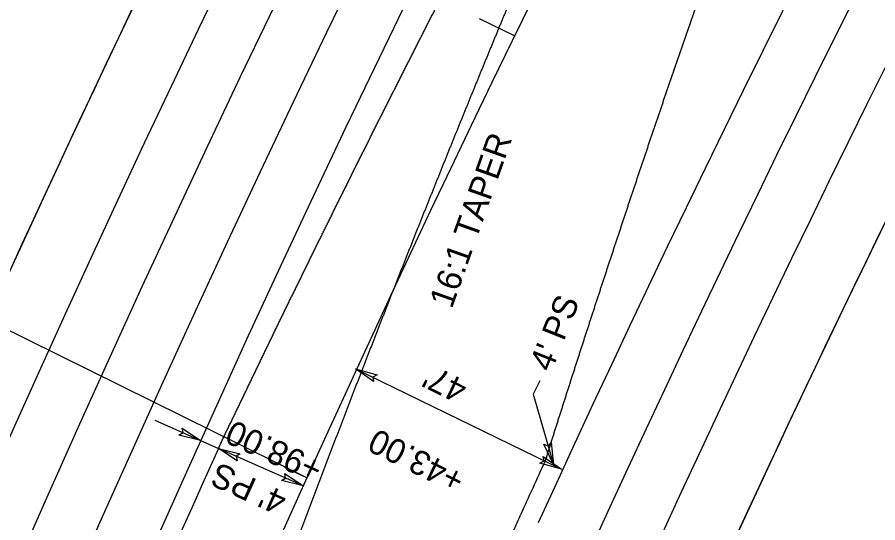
# Model space of a CAD drawing. Extents: x 2389099 to 2405615, y 552200 to 573532.
# Drawn here: x 2395482.3 to 2395658.7, y 556915.3 to 557018.8 of the extents above; entities that cross this region are included whole.
import ezdxf

# ---------------------------------------------------------------- set-up
doc = ezdxf.new("R2010")
doc.units = 0
for name, color, linetype in [('Prop Cable Guiderail Single Face', 7, 'Continuous'), ('Prop Dimension', 7, 'Continuous'), ('Prop Dimension Text', 7, 'Continuous'), ('Prop DSN Text', 7, 'Continuous'), ('Prop EOT', 7, 'Continuous'), ('Prop Guardrail', 7, 'Continuous'), ('Prop Horizontal Alignment', 7, 'Continuous'), ('Prop Horizontal Alignment Tick Large', 7, 'Continuous'), ('Prop Horizontal Alignment Tick Small', 7, 'Continuous'), ('Prop Lane Lines', 7, 'Continuous'), ('Prop SBG', 7, 'Continuous')]:
    doc.layers.add(name, color=color, linetype=linetype)

msp = doc.modelspace()

# ---------------------------------------------------------------- linework, layer by layer
at = {"layer": 'Prop Cable Guiderail Single Face'}
for points in [[(2395600.36, 557062.59), (2395600.06, 557061.88), (2395599.75, 557061.17), (2395599.44, 557060.45), (2395599.14, 557059.74), (2395598.83, 557059.03), (2395598.53, 557058.31), (2395598.22, 557057.6), (2395597.92, 557056.88), (2395597.61, 557056.17), (2395597.31, 557055.46), (2395597, 557054.74), (2395596.7, 557054.03), (2395596.4, 557053.32), (2395596.09, 557052.61), (2395595.79, 557051.89), (2395595.48, 557051.18), (2395595.18, 557050.47), (2395594.88, 557049.76), (2395594.57, 557049.04), (2395594.27, 557048.32), (2395593.97, 557047.61), (2395593.67, 557046.9), (2395593.36, 557046.18), (2395593.06, 557045.47), (2395592.76, 557044.76), (2395592.46, 557044.05), (2395592.15, 557043.33), (2395591.85, 557042.61), (2395591.55, 557041.9), (2395591.25, 557041.19), (2395590.95, 557040.47), (2395590.65, 557039.76), (2395590.35, 557039.04), (2395590.05, 557038.33), (2395589.75, 557037.61), (2395589.45, 557036.9), (2395589.15, 557036.19), (2395588.85, 557035.47), (2395588.55, 557034.76), (2395588.25, 557034.04), (2395587.95, 557033.33), (2395587.65, 557032.61), (2395587.35, 557031.9), (2395587.05, 557031.18), (2395586.75, 557030.47), (2395586.45, 557029.75), (2395586.16, 557029.04), (2395585.85, 557028.32), (2395585.56, 557027.61), (2395585.26, 557026.89), (2395584.96, 557026.18), (2395584.66, 557025.46), (2395584.37, 557024.75), (2395584.07, 557024.03), (2395583.77, 557023.32), (2395583.47, 557022.6), (2395583.18, 557021.88), (2395582.88, 557021.17), (2395582.59, 557020.46), (2395582.29, 557019.73), (2395581.99, 557019.02), (2395581.7, 557018.31), (2395581.4, 557017.59), (2395581.1, 557016.87), (2395580.81, 557016.16), (2395580.51, 557015.44), (2395580.22, 557014.73), (2395579.92, 557014), (2395579.63, 557013.29), (2395579.33, 557012.58), (2395579.04, 557011.86), (2395578.74, 557011.14), (2395578.45, 557010.42), (2395578.15, 557009.71)], [(2395578.15, 557009.71), (2395577.86, 557008.99), (2395577.57, 557008.28), (2395577.27, 557007.56), (2395576.98, 557006.84), (2395576.69, 557006.13), (2395576.39, 557005.41), (2395576.1, 557004.69), (2395575.81, 557003.97), (2395575.51, 557003.26), (2395575.22, 557002.54), (2395574.93, 557001.82), (2395574.64, 557001.1), (2395574.35, 557000.39), (2395574.05, 556999.67), (2395573.76, 556998.95), (2395573.47, 556998.24), (2395573.18, 556997.52), (2395572.89, 556996.8), (2395572.59, 556996.08), (2395572.3, 556995.36), (2395572.01, 556994.65), (2395571.72, 556993.93), (2395571.43, 556993.21), (2395571.14, 556992.49), (2395570.85, 556991.78), (2395570.56, 556991.06), (2395570.27, 556990.34), (2395569.98, 556989.62), (2395569.69, 556988.9), (2395569.41, 556988.19), (2395569.11, 556987.46), (2395568.83, 556986.75), (2395568.54, 556986.03), (2395568.25, 556985.31), (2395567.96, 556984.59), (2395567.67, 556983.87), (2395567.38, 556983.16), (2395567.1, 556982.44), (2395566.81, 556981.72), (2395566.52, 556981), (2395566.23, 556980.28), (2395565.95, 556979.56), (2395565.66, 556978.85), (2395565.37, 556978.12), (2395565.08, 556977.4), (2395564.8, 556976.69), (2395564.51, 556975.97), (2395564.22, 556975.24), (2395563.94, 556974.53), (2395563.65, 556973.81), (2395563.37, 556973.09), (2395563.08, 556972.37), (2395562.8, 556971.65), (2395562.51, 556970.93), (2395562.23, 556970.22), (2395561.94, 556969.49), (2395561.65, 556968.77), (2395561.37, 556968.05), (2395561.09, 556967.34), (2395560.8, 556966.61), (2395560.52, 556965.89), (2395560.23, 556965.17), (2395559.95, 556964.46), (2395559.66, 556963.73), (2395559.38, 556963.01), (2395559.1, 556962.29), (2395558.82, 556961.58), (2395558.53, 556960.85), (2395558.25, 556960.13), (2395557.97, 556959.41), (2395557.69, 556958.69), (2395557.4, 556957.97), (2395557.12, 556957.25), (2395556.84, 556956.53)], [(2395556.84, 556956.53), (2395556.56, 556955.81), (2395556.28, 556955.09), (2395555.99, 556954.36), (2395555.71, 556953.65), (2395555.43, 556952.93), (2395555.15, 556952.21), (2395554.87, 556951.48), (2395554.59, 556950.76), (2395554.31, 556950.04), (2395554.03, 556949.32), (2395553.74, 556948.6), (2395553.46, 556947.88), (2395553.19, 556947.16), (2395552.91, 556946.44), (2395552.62, 556945.71), (2395552.35, 556944.99), (2395552.07, 556944.27), (2395551.79, 556943.55), (2395551.51, 556942.82), (2395551.23, 556942.11), (2395550.95, 556941.39), (2395550.67, 556940.67), (2395550.39, 556939.94), (2395550.12, 556939.22), (2395549.84, 556938.5), (2395549.56, 556937.78), (2395549.28, 556937.05), (2395549, 556936.33), (2395548.73, 556935.61), (2395548.45, 556934.89), (2395548.17, 556934.16), (2395547.9, 556933.44), (2395547.62, 556932.72), (2395547.34, 556932), (2395547.06, 556931.27), (2395546.79, 556930.55), (2395546.51, 556929.83), (2395546.24, 556929.11), (2395545.97, 556928.39), (2395545.69, 556927.66), (2395545.41, 556926.94), (2395545.14, 556926.22), (2395544.86, 556925.5), (2395544.59, 556924.77), (2395544.31, 556924.05), (2395544.04, 556923.33), (2395543.76, 556922.61), (2395543.49, 556921.88), (2395543.21, 556921.16), (2395542.94, 556920.43), (2395542.67, 556919.71), (2395542.39, 556918.98), (2395542.12, 556918.26), (2395541.85, 556917.54), (2395541.58, 556916.82), (2395541.3, 556916.09), (2395541.03, 556915.37), (2395540.76, 556914.65), (2395540.48, 556913.93), (2395540.21, 556913.19), (2395539.94, 556912.47), (2395539.67, 556911.75), (2395539.4, 556911.03), (2395539.12, 556910.3), (2395538.85, 556909.58), (2395538.58, 556908.86), (2395538.31, 556908.13), (2395538.04, 556907.4), (2395537.77, 556906.68), (2395537.5, 556905.96), (2395537.23, 556905.24), (2395536.95, 556904.51), (2395536.42, 556903.06)]]:
    msp.add_spline(points, degree=3, dxfattribs=at)
at = {"layer": 'Prop Dimension'}
for p, q in [((2395551.61, 556946.84), (2395593.85, 556926.23)), ((2395589.43, 556944.33), (2395588.08, 556941.6)), ((2395588.08, 556941.6), (2395592.22, 556927.2)), ((2395510.47, 556936.31), (2395523.53, 556930.52)), ((2395540.9, 556922.82), (2395523.53, 556930.52))]:
    msp.add_line(p, q, dxfattribs=at)
for points in [[(2395555.33, 556944.19), (2395551.61, 556946.84), (2395556.04, 556945.6), (2395555.17, 556945.13)], [(2395516.07, 556934.67), (2395519.87, 556932.14), (2395515.41, 556933.24), (2395516.26, 556933.74)], [(2395591.73, 556931.74), (2395592.22, 556927.2), (2395590.21, 556931.34), (2395591.14, 556931)], [(2395527.33, 556927.99), (2395523.53, 556930.52), (2395527.99, 556929.42), (2395527.14, 556928.92)], [(2395590.13, 556928.88), (2395593.85, 556926.23), (2395589.43, 556927.47), (2395590.29, 556927.94)], [(2395537.1, 556925.35), (2395540.9, 556922.82), (2395536.44, 556923.92), (2395537.29, 556924.42)]]:
    msp.add_lwpolyline(points, close=True, dxfattribs=at)
at = {"layer": 'Prop DSN Text'}
msp.add_line((2395541.67, 556924.51), (2395466.55, 556961.59), dxfattribs=at)
at = {"layer": 'Prop EOT'}
msp.add_line((2395523.56, 556930.54), (2395523.3, 556930), dxfattribs=at)
for centre, radius, start, end in [((2398729.82, 555480.32), 3559, 136.54853, 163.17888), ((2398729.82, 555480.32), 3523, 136.54853, 169.40696), ((2398729.82, 555480.32), 3453, 136.54853, 155.44499), ((2398729.82, 555480.32), 3429, 136.54853, 155.44499), ((2398729.82, 555480.32), 3573, 151.19964, 163.17888), ((2398729.83, 555480.34), 3415, 150.73536, 155.44499), ((2398729.82, 555480.32), 3519, 155.66284, 169.40696), ((2398729.82, 555480.32), 3457, 155.2472, 155.44499)]:
    msp.add_arc(centre, radius, start, end, dxfattribs=at)
for points in [[(2395553, 556990.89), (2395553.41, 556991.7), (2395553.81, 556992.51), (2395554.22, 556993.32), (2395554.63, 556994.13), (2395555.03, 556994.94), (2395555.44, 556995.75), (2395555.85, 556996.56), (2395556.26, 556997.38), (2395556.66, 556998.19), (2395557.07, 556999), (2395557.48, 556999.81), (2395557.89, 557000.62), (2395558.3, 557001.43), (2395558.7, 557002.24), (2395559.11, 557003.05), (2395559.52, 557003.86), (2395559.93, 557004.67), (2395560.34, 557005.48), (2395560.75, 557006.29), (2395561.16, 557007.1), (2395561.57, 557007.91), (2395561.98, 557008.72), (2395562.39, 557009.53), (2395562.8, 557010.34), (2395563.21, 557011.15), (2395563.63, 557011.95), (2395564.04, 557012.76), (2395564.45, 557013.57), (2395564.86, 557014.38), (2395565.27, 557015.19), (2395565.69, 557016), (2395566.1, 557016.81), (2395566.51, 557017.61), (2395566.92, 557018.42), (2395567.34, 557019.23), (2395567.75, 557020.04), (2395568.16, 557020.85), (2395568.58, 557021.65), (2395568.99, 557022.46), (2395569.4, 557023.27), (2395569.82, 557024.08), (2395570.23, 557024.88), (2395570.65, 557025.69), (2395571.06, 557026.5), (2395571.48, 557027.3), (2395571.89, 557028.11), (2395572.31, 557028.92), (2395572.73, 557029.72), (2395573.14, 557030.53), (2395573.56, 557031.34), (2395573.97, 557032.14), (2395574.39, 557032.95), (2395574.81, 557033.75), (2395575.22, 557034.56), (2395575.64, 557035.37), (2395576.06, 557036.17), (2395576.48, 557036.98), (2395576.89, 557037.78), (2395577.31, 557038.59), (2395577.73, 557039.39), (2395578.15, 557040.2), (2395578.57, 557041), (2395578.99, 557041.81), (2395579.41, 557042.61), (2395579.82, 557043.42), (2395580.24, 557044.22), (2395580.66, 557045.03), (2395581.08, 557045.83), (2395581.5, 557046.64), (2395581.92, 557047.44), (2395582.34, 557048.24), (2395582.77, 557049.05), (2395583.19, 557049.85), (2395583.61, 557050.65)], [(2395629.58, 557044.33), (2395629.3, 557043.54), (2395629.02, 557042.76), (2395628.75, 557041.98), (2395628.47, 557041.19), (2395628.19, 557040.4), (2395627.91, 557039.62), (2395627.63, 557038.84), (2395627.36, 557038.06), (2395627.08, 557037.26), (2395626.8, 557036.48), (2395626.53, 557035.7), (2395626.25, 557034.92), (2395625.97, 557034.13), (2395625.69, 557033.34), (2395625.42, 557032.56), (2395625.14, 557031.77), (2395624.87, 557030.99), (2395624.59, 557030.2), (2395624.32, 557029.42), (2395624.04, 557028.63), (2395623.76, 557027.85), (2395623.49, 557027.06), (2395623.22, 557026.28), (2395622.94, 557025.49), (2395622.67, 557024.7), (2395622.39, 557023.92), (2395622.12, 557023.14), (2395621.84, 557022.35), (2395621.57, 557021.56), (2395621.3, 557020.78), (2395621.03, 557020), (2395620.75, 557019.2), (2395620.48, 557018.42), (2395620.21, 557017.64), (2395619.93, 557016.84), (2395619.66, 557016.06), (2395619.39, 557015.28), (2395619.12, 557014.49), (2395618.85, 557013.7), (2395618.57, 557012.92), (2395618.3, 557012.13), (2395618.04, 557011.35), (2395617.76, 557010.56), (2395617.49, 557009.77), (2395617.22, 557008.99), (2395616.95, 557008.2), (2395616.68, 557007.41), (2395616.41, 557006.63), (2395616.14, 557005.84), (2395615.88, 557005.06), (2395615.6, 557004.27), (2395615.34, 557003.48), (2395615.07, 557002.7), (2395614.8, 557001.91), (2395614.53, 557001.12), (2395614.26, 557000.33), (2395613.99, 556999.55), (2395613.72, 556998.76), (2395613.46, 556997.97), (2395613.19, 556997.19), (2395612.92, 556996.4), (2395612.65, 556995.61), (2395612.39, 556994.82), (2395612.12, 556994.04), (2395611.86, 556993.25), (2395611.59, 556992.46), (2395611.32, 556991.68), (2395611.06, 556990.89), (2395610.8, 556990.11), (2395610.53, 556989.31), (2395610.26, 556988.53), (2395610, 556987.74), (2395609.74, 556986.96), (2395609.47, 556986.16)], [(2395523.53, 556930.52), (2395523.92, 556931.34), (2395524.31, 556932.16), (2395524.7, 556932.98), (2395525.09, 556933.8), (2395525.49, 556934.62), (2395525.88, 556935.44), (2395526.27, 556936.25), (2395526.66, 556937.07), (2395527.05, 556937.89), (2395527.45, 556938.71), (2395527.84, 556939.53), (2395528.23, 556940.35), (2395528.63, 556941.17), (2395529.02, 556941.98), (2395529.41, 556942.8), (2395529.81, 556943.62), (2395530.2, 556944.44), (2395530.59, 556945.26), (2395530.99, 556946.07), (2395531.38, 556946.89), (2395531.78, 556947.71), (2395532.17, 556948.53), (2395532.57, 556949.34), (2395532.96, 556950.16), (2395533.36, 556950.98), (2395533.76, 556951.8), (2395534.15, 556952.61), (2395534.55, 556953.43), (2395534.94, 556954.25), (2395535.34, 556955.06), (2395535.74, 556955.88), (2395536.13, 556956.7), (2395536.53, 556957.51), (2395536.93, 556958.33), (2395537.33, 556959.14), (2395537.73, 556959.96), (2395538.12, 556960.78), (2395538.52, 556961.59), (2395538.92, 556962.41), (2395539.32, 556963.22), (2395539.72, 556964.04), (2395540.12, 556964.85), (2395540.52, 556965.67), (2395540.92, 556966.48), (2395541.32, 556967.3), (2395541.72, 556968.11), (2395542.12, 556968.93), (2395542.52, 556969.74), (2395542.92, 556970.56), (2395543.32, 556971.37), (2395543.72, 556972.19), (2395544.12, 556973), (2395544.52, 556973.81), (2395544.92, 556974.63), (2395545.33, 556975.44), (2395545.73, 556976.26), (2395546.13, 556977.07), (2395546.53, 556977.88), (2395546.94, 556978.7), (2395547.34, 556979.51), (2395547.74, 556980.32), (2395548.14, 556981.14), (2395548.55, 556981.95), (2395548.95, 556982.76), (2395549.36, 556983.57), (2395549.76, 556984.39), (2395550.16, 556985.2), (2395550.57, 556986.01), (2395550.97, 556986.82), (2395551.38, 556987.64), (2395551.78, 556988.45), (2395552.19, 556989.26), (2395552.6, 556990.07), (2395553, 556990.89)], [(2395609.47, 556986.16), (2395609.2, 556985.38), (2395608.94, 556984.59), (2395608.68, 556983.81), (2395608.41, 556983.01), (2395608.15, 556982.23), (2395607.89, 556981.44), (2395607.62, 556980.65), (2395607.36, 556979.86), (2395607.1, 556979.08), (2395606.83, 556978.29), (2395606.57, 556977.5), (2395606.31, 556976.71), (2395606.05, 556975.92), (2395605.79, 556975.14), (2395605.52, 556974.34), (2395605.26, 556973.56), (2395605, 556972.77), (2395604.74, 556971.99), (2395604.48, 556971.19), (2395604.22, 556970.41), (2395603.96, 556969.62), (2395603.7, 556968.83), (2395603.44, 556968.04), (2395603.18, 556967.25), (2395602.92, 556966.47), (2395602.66, 556965.67), (2395602.4, 556964.89), (2395602.14, 556964.1), (2395601.88, 556963.31), (2395601.62, 556962.52), (2395601.36, 556961.73), (2395601.11, 556960.94), (2395600.85, 556960.16), (2395600.59, 556959.36), (2395600.33, 556958.58), (2395600.08, 556957.79), (2395599.82, 556957), (2395599.56, 556956.21), (2395599.3, 556955.42), (2395599.05, 556954.63), (2395598.79, 556953.85), (2395598.53, 556953.05), (2395598.28, 556952.26), (2395598.02, 556951.48), (2395597.77, 556950.69), (2395597.51, 556949.89), (2395597.26, 556949.11), (2395597, 556948.32), (2395596.74, 556947.52), (2395596.49, 556946.74), (2395596.24, 556945.95), (2395595.98, 556945.16), (2395595.73, 556944.37), (2395595.47, 556943.58), (2395595.22, 556942.79), (2395594.97, 556942), (2395594.71, 556941.21), (2395594.46, 556940.42), (2395594.21, 556939.63), (2395593.96, 556938.85), (2395593.7, 556938.05), (2395593.45, 556937.26), (2395593.2, 556936.47), (2395592.95, 556935.69), (2395592.69, 556934.89), (2395592.44, 556934.1), (2395592.19, 556933.31), (2395591.94, 556932.53), (2395591.69, 556931.73), (2395591.44, 556930.94), (2395591.19, 556930.15), (2395590.94, 556929.36), (2395590.44, 556927.78)], [(2395585.46, 556916.93), (2395584.33, 556914.46), (2395583.21, 556911.99), (2395582.08, 556909.52), (2395580.96, 556907.05), (2395579.84, 556904.57), (2395578.73, 556902.09), (2395577.61, 556899.62), (2395576.5, 556897.14), (2395575.39, 556894.66), (2395574.28, 556892.18), (2395573.17, 556889.69), (2395572.07, 556887.21), (2395570.96, 556884.72), (2395569.86, 556882.23), (2395568.77, 556879.74), (2395567.67, 556877.26), (2395566.58, 556874.76), (2395565.49, 556872.27), (2395564.41, 556869.77), (2395563.32, 556867.28), (2395562.24, 556864.78), (2395561.16, 556862.28), (2395560.09, 556859.78), (2395559.02, 556857.28), (2395557.95, 556854.77), (2395556.88, 556852.27), (2395555.82, 556849.76), (2395554.76, 556847.25), (2395553.7, 556844.74), (2395552.65, 556842.22), (2395551.6, 556839.71), (2395550.56, 556837.19), (2395549.51, 556834.67), (2395548.47, 556832.15), (2395547.44, 556829.63), (2395546.41, 556827.11), (2395545.38, 556824.58), (2395544.35, 556822.06), (2395543.33, 556819.53), (2395542.31, 556817), (2395541.3, 556814.46), (2395540.29, 556811.93), (2395539.29, 556809.39), (2395538.29, 556806.85), (2395537.29, 556804.31), (2395536.3, 556801.77), (2395535.31, 556799.22), (2395534.32, 556796.68), (2395533.34, 556794.13), (2395532.37, 556791.58), (2395531.4, 556789.03), (2395530.43, 556786.47), (2395529.47, 556783.91), (2395528.51, 556781.36), (2395527.56, 556778.79), (2395526.61, 556776.23), (2395525.66, 556773.67), (2395524.72, 556771.1), (2395523.79, 556768.53), (2395522.86, 556765.96), (2395521.94, 556763.38), (2395521.02, 556760.81), (2395520.1, 556758.23), (2395519.19, 556755.65), (2395518.29, 556753.07), (2395517.39, 556750.48), (2395516.5, 556747.9), (2395515.61, 556745.31), (2395514.73, 556742.72), (2395513.85, 556740.13), (2395512.98, 556737.53), (2395512.11, 556734.93), (2395511.25, 556732.33), (2395510.41, 556729.75)]]:
    msp.add_spline(points, degree=3, dxfattribs=at)
at = {"layer": 'Prop Guardrail'}
for radius, start, end in [(3573, 151.45837, 163.17888), (3415, 149.9922, 155.44499)]:
    msp.add_arc((2398729.82, 555480.32), radius, start, end, dxfattribs=at)
at = {"layer": 'Prop Horizontal Alignment'}
msp.add_arc((2398729.82, 555480.32), 3500, 136.54853, 177.15578, dxfattribs=at)
at = {"layer": 'Prop Horizontal Alignment Tick Large'}
msp.add_line((2395584.23, 557015), (2395577.04, 557018.51), dxfattribs=at)
at = {"layer": 'Prop Horizontal Alignment Tick Small'}
msp.add_line((2395541.67, 556924.51), (2395537.11, 556926.57), dxfattribs=at)
at = {"layer": 'Prop Lane Lines'}
for radius, end in [(3547, 169.40696), (3535, 169.40696), (3441, 155.44499)]:
    msp.add_arc((2398729.82, 555480.32), radius, 136.54853, end, dxfattribs=at)
at = {"layer": 'Prop SBG'}
msp.add_arc((2398729.82, 555480.32), 3415, 149.9922, 155.44499, dxfattribs=at)

# ---------------------------------------------------------------- texts
at = {"layer": 'Prop Dimension Text'}
for s, rotation, p in [('16:1 TAPER', 70.4786, (2395571.37, 556958.98)), ("4' PS", 68.3018, (2395591.78, 556945.96)), ("47'", 153.764, (2395574.94, 556944)), ('+98.00', 155.5159, (2395545.35, 556927.89)), ('+43.00', 153.764, (2395574.46, 556925.58)), ("4' PS", 155.5159, (2395537.92, 556921.21))]:
    msp.add_text(s, height=5, rotation=rotation, dxfattribs=at).set_placement(p)

doc.saveas('drawing.dxf')
